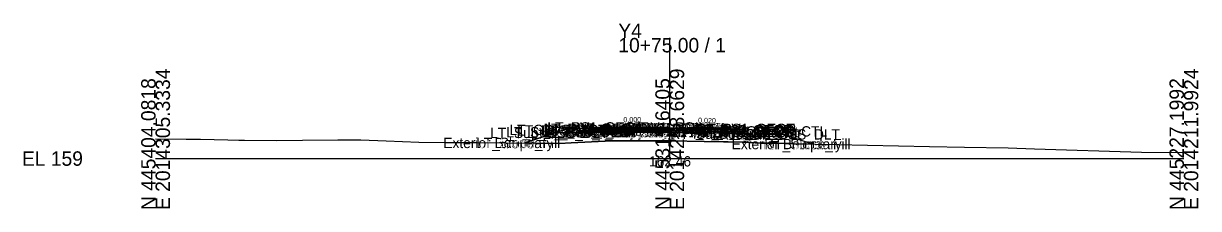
# Model space of a CAD drawing. Extents: x -26 to 203, y -10 to 4021.
# Drawn here: x -25.7 to 202.8, y 1490.3 to 1526.2 of the extents above; entities that cross this region are included whole.
import ezdxf

# ---------------------------------------------------------------- set-up
doc = ezdxf.new("R2010")
doc.units = 0
for name, color, linetype in [('Default', 7, 'Continuous'), ('Exist Cross Section Cell', 7, 'Continuous'), ('Exist XS Center Line Elevation Label', 7, 'Continuous'), ('Exist XS Ground Line', 7, 'Continuous'), ('Prop CMT Pvmt Course 1', 7, 'Continuous'), ('Prop CMT Pvmt Course 2', 7, 'Continuous'), ('Prop CMT Pvmt Course 3', 7, 'Continuous'), ('Prop CMT Pvmt Surface', 7, 'Continuous'), ('Prop CMT Pvmt Surface Shoulder', 7, 'Continuous'), ('Prop CMT Shld Paved Course 1', 7, 'Continuous'), ('Prop CMT Shld Paved Course 2', 7, 'Continuous'), ('Prop CMT Shld Paved Course 3', 7, 'Continuous'), ('Prop CMT Slope Grass', 7, 'Continuous'), ('Prop CMT Subgrade Earthwork', 7, 'Continuous'), ('Prop XS Earthwork Shape', 7, 'Continuous'), ('Prop XS SE Text', 7, 'Continuous'), ('Prop XS Side Slope Text', 7, 'Continuous'), ('Scratch_Level_0', 7, 'Continuous')]:
    doc.layers.add(name, color=color, linetype=linetype)

msp = doc.modelspace()

# ---------------------------------------------------------------- linework, layer by layer
at = {"layer": 'Exist Cross Section Cell'}
for p, q in [((100, 1500), (100, 1523.42)), ((0, 1500), (100, 1500)), ((100, 1500), (200, 1500))]:
    msp.add_line(p, q, dxfattribs=at)
at = {"layer": 'Exist XS Ground Line'}
msp.add_lwpolyline([(0, 1503.82), (5.97, 1503.78), (8.76, 1503.74), (14.03, 1503.64), (16.16, 1503.54), (17.28, 1503.56), (23.56, 1503.5), (28.59, 1503.6), (35.46, 1503.64), (38.37, 1503.64), (39.9, 1503.64), (44.85, 1503.43), (51.21, 1503.18), (56.89, 1503.13), (60.57, 1503.15), (62.51, 1503.13), (73.89, 1503), (78.53, 1502.91), (80.82, 1503.08), (88.74, 1503.44), (95.3, 1503.45), (99.31, 1503.47), (100, 1503.46), (106.7, 1503.34), (114.24, 1503.16), (117.81, 1502.97), (119.69, 1502.98), (122.52, 1502.91), (123.46, 1502.91), (124.13, 1502.89), (132.44, 1502.71), (150.49, 1502.33), (157.31, 1502.23), (165.84, 1502.09), (170.93, 1501.89), (191.73, 1501.27), (200, 1501.15)], dxfattribs=at)
at = {"layer": 'Prop CMT Pvmt Course 1'}
for points in [[(100, 1506.05), (85.45, 1506.05)], [(85.45, 1506.05), (85.45, 1505.8)], [(100, 1505.8), (100, 1506.05)], [(100, 1506.05), (114.47, 1505.76)], [(100, 1505.8), (100, 1506.05)], [(85.45, 1505.8), (100, 1505.8)], [(114.47, 1505.51), (100, 1505.8)], [(114.47, 1505.76), (114.47, 1505.51)]]:
    msp.add_lwpolyline(points, dxfattribs=at)
msp.add_lwpolyline([(100, 1505.8), (100, 1505.93), (100, 1505.93), (100, 1505.8)], close=True, dxfattribs=at)
msp.add_lwpolyline([(100, 1505.8), (100, 1505.93), (100, 1505.93), (100, 1505.8)], close=True, dxfattribs=at)
at = {"layer": 'Prop CMT Pvmt Course 2'}
for points in [[(100, 1505.8), (85.45, 1505.8)], [(85.45, 1505.8), (85.45, 1505.47)], [(85.45, 1505.47), (100, 1505.47)], [(100, 1505.47), (100, 1505.8)], [(100, 1505.47), (100, 1505.8)], [(100, 1505.8), (114.47, 1505.51)], [(114.47, 1505.18), (100, 1505.47)], [(114.47, 1505.51), (114.47, 1505.18)]]:
    msp.add_lwpolyline(points, dxfattribs=at)
at = {"layer": 'Prop CMT Pvmt Course 3'}
for points in [[(100, 1505.47), (85.45, 1505.47)], [(85.45, 1505.47), (85.45, 1505.13)], [(85.45, 1505.13), (100, 1505.13)], [(100, 1505.13), (100, 1505.47)], [(100, 1505.47), (114.47, 1505.18)], [(100, 1505.13), (100, 1505.47)], [(114.47, 1504.84), (100, 1505.13)], [(114.47, 1505.18), (114.47, 1504.84)]]:
    msp.add_lwpolyline(points, dxfattribs=at)
at = {"layer": 'Prop CMT Pvmt Surface'}
for points in [[(100, 1506.05), (85.45, 1506.05)], [(100, 1506.05), (114.47, 1505.76)]]:
    msp.add_lwpolyline(points, dxfattribs=at)
at = {"layer": 'Prop CMT Pvmt Surface Shoulder'}
for points in [[(85.45, 1506.05), (85.45, 1506.05)], [(114.47, 1505.76), (114.47, 1505.76)]]:
    msp.add_lwpolyline(points, dxfattribs=at)
at = {"layer": 'Prop CMT Shld Paved Course 1'}
for points in [[(85.45, 1506.05), (85.2, 1505.8)], [(85.45, 1506.05), (85.45, 1506.05)], [(85.45, 1505.8), (85.45, 1506.05)], [(85.2, 1505.8), (85.45, 1505.8)], [(114.47, 1505.76), (114.47, 1505.76)], [(114.47, 1505.76), (114.73, 1505.51)], [(114.47, 1505.51), (114.47, 1505.76)], [(114.73, 1505.51), (114.47, 1505.51)]]:
    msp.add_lwpolyline(points, dxfattribs=at)
at = {"layer": 'Prop CMT Shld Paved Course 2'}
for points in [[(85.45, 1505.8), (85.2, 1505.8), (84.86, 1505.46)], [(84.86, 1505.46), (85.45, 1505.47)], [(85.45, 1505.47), (85.45, 1505.8)], [(114.47, 1505.51), (114.73, 1505.51), (115.07, 1505.17)], [(114.47, 1505.18), (114.47, 1505.51)], [(115.07, 1505.17), (114.47, 1505.18)]]:
    msp.add_lwpolyline(points, dxfattribs=at)
at = {"layer": 'Prop CMT Shld Paved Course 3'}
for points in [[(84.02, 1505.11), (85.45, 1505.13)], [(85.45, 1505.47), (84.86, 1505.46), (84.52, 1505.12)], [(85.45, 1505.13), (85.45, 1505.47)], [(114.47, 1504.84), (114.47, 1505.18)], [(114.47, 1505.18), (115.07, 1505.17), (115.41, 1504.83)], [(115.91, 1504.82), (114.47, 1504.84)]]:
    msp.add_lwpolyline(points, dxfattribs=at)
at = {"layer": 'Prop CMT Slope Grass'}
for points in [[(85.45, 1506.05), (79.45, 1505.57), (71.82, 1503.03)], [(114.47, 1505.76), (120.47, 1505.28), (127.9, 1502.81)]]:
    msp.add_lwpolyline(points, dxfattribs=at)
at = {"layer": 'Prop CMT Subgrade Earthwork'}
for points in [[(84.02, 1505.11), (77.68, 1504.98)], [(85.45, 1505.13), (84.02, 1505.11)], [(100, 1505.13), (85.45, 1505.13)], [(100, 1505.13), (114.47, 1504.84)], [(114.47, 1504.84), (115.91, 1504.82)], [(115.91, 1504.82), (122.25, 1504.69)]]:
    msp.add_lwpolyline(points, dxfattribs=at)
at = {"layer": 'Prop XS Earthwork Shape'}
msp.add_lwpolyline([(115.91, 1504.82), (122.25, 1504.69), (127.9, 1502.81), (124.13, 1502.89), (123.46, 1502.91), (122.52, 1502.91), (119.69, 1502.98), (117.81, 1502.97), (114.24, 1503.16), (106.7, 1503.34), (100, 1503.46), (99.31, 1503.47), (95.3, 1503.45), (88.74, 1503.44), (80.82, 1503.08), (78.53, 1502.91), (73.89, 1503), (71.82, 1503.03), (77.68, 1504.98), (84.02, 1505.11), (85.45, 1505.13), (100, 1505.13), (114.47, 1504.84)], close=True, dxfattribs=at)

# ---------------------------------------------------------------- texts
at = {"layer": 'Default'}
msp.add_text('-', height=0.0001, dxfattribs=at).set_placement((0, 1500))
at = {"layer": 'Exist Cross Section Cell'}
for s, p in [('Y4', (90, 1523.42)), ('10+75.00 / 1', (90, 1520.62)), ('EL 159', (-26, 1498.6))]:
    msp.add_text(s, height=2.8, dxfattribs=at).set_placement(p)
for s, p in [('N 445404.0818', (0, 1490)), ('E 2014305.3334', (2.8, 1490)), ('N 445315.6405', (100, 1490)), ('E 2014258.6629', (102.8, 1490)), ('N 445227.1992', (200, 1490)), ('E 2014211.9924', (202.8, 1490))]:
    msp.add_text(s, height=2.8, rotation=90, dxfattribs=at).set_placement(p)
at = {"layer": 'Exist XS Center Line Elevation Label'}
msp.add_text('162.46', height=2, dxfattribs=at).set_placement((95.97, 1498.46))
at = {"layer": 'Prop XS SE Text'}
msp.add_text('0.000', height=1, dxfattribs=at).set_placement((90.98, 1507.05))
msp.add_text('0.020', height=1, rotation=358.8542, dxfattribs=at).set_placement((105.51, 1506.94))
at = {"layer": 'Prop XS Side Slope Text'}
for rotation, p in [(18.4332, (74.65, 1504.76)), (341.5668, (123.67, 1505.01))]:
    msp.add_text('3:1', height=1, rotation=rotation, dxfattribs=at).set_placement(p)
at = {"layer": 'Scratch_Level_0'}
for s, p in [('LT_Sub_OSS_DLT', (65.08, 1503.98)), ('LT_Sub_Trench_Out', (68.22, 1504.11)), ('LT_GS_OS_CTL', (68.82, 1504.57)), ('LT_PS3_Shelf_Out', (70.34, 1504.45)), ('LT_PS3_OEOP', (75.09, 1504.46)), ('LT_PS2_OEOP', (75.43, 1504.8)), ('LT_Sub_OEOT', (75.53, 1504.13)), ('LT_PV2_OEOT', (75.63, 1504.8)), ('LT_PV3_OEOT', (75.63, 1504.47)), ('LT_PV1_OEOT', (76.19, 1505.05)), ('LT_PS1_OEOP', (76.26, 1505.05)), ('RT_Sub_OEEOP', (89.17, 1504.13)), ('LT_Sub_OEEOP', (89.21, 1504.13)), ('RT_PV2_OEEOP', (89.26, 1504.8)), ('RT_PV3_OEEOP', (89.26, 1504.47)), ('LT_PV2_OEEOP', (89.31, 1504.8)), ('LT_PV3_OEEOP', (89.31, 1504.47)), ('RT_PV1_OEEOP', (89.83, 1504.93)), ('LT_PV1_OEEOP', (89.87, 1504.93)), ('RT_PV2_IEEOP', (89.91, 1504.8)), ('LT_PV2_IEEOP', (89.95, 1504.8)), ('RT_PV1_IEEOP', (90.47, 1504.93)), ('LT_PV1_IEEOP', (90.52, 1504.93)), ('PV2_PGL', (93.91, 1504.8)), ('PV1_PGL', (94.47, 1505.05)), ('RT_PS3_Shelf_Out', (101.51, 1504.16)), ('RT_PV2_OEOT', (104.6, 1504.51)), ('RT_PV3_OEOT', (104.6, 1504.18)), ('RT_PS2_OEOP', (104.92, 1504.51)), ('RT_PV1_OEOT', (105.17, 1504.76)), ('RT_PS1_OEOP', (105.23, 1504.76)), ('RT_PS3_OEOP', (105.26, 1504.17)), ('RT_GS_OS_CTL', (109.8, 1504.28)), ('Exterior Boundary', (55.96, 1502.03)), ('LT_Slope_Fill', (62.34, 1502.03)), ('RT_Sub_Trench_Out', (100.07, 1503.82)), ('RT_Sub_OEOT', (104.51, 1503.84)), ('RT_Sub_OSS_DLT', (109.61, 1503.69)), ('Exterior Boundary', (112.04, 1501.81)), ('RT_Slope_Fill', (118.37, 1501.81))]:
    msp.add_text(s, height=2, dxfattribs=at).set_placement(p)

doc.saveas('drawing.dxf')
